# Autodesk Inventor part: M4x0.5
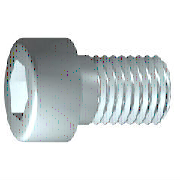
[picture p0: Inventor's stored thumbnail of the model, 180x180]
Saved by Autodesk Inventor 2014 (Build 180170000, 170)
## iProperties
IsCustomPart: 1
Company: 한국ATC센터
Created: 2009-02
Part Number: M4x0.5
Material: 강, 연강
Description: 6각머리 태핑 나사
Document SubType Name: Modeling
Standard: KS B 1003
Designer: KYOUNG IL JANG
Standards Organization: KS
Language: ko-KR
Size Designation: M 4 x 12
Categories: <MemberInstance><Categories><Category DisplayName="조임쇠" InternalName="e4da775c-781d-43d5-af7c-5136215cf5a6" Mnemonic="FSTN"><Category DisplayName="볼트" InternalN
Density: 1 g/cm^3
Appearance: 강철
Author: KYOUNG IL JANG
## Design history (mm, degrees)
sketch "스케치1"
  geometry: L1 (-1, 0)-(12, 0); L2 (12, 0)-(12, 2); L3 (12, 2)-(1.75, 2); L4 (1.75, 2)-(1.32, 2); L5 (1.32, 2)-(0, 2); L6 (0, 2)-(0, 3.5); L7 (0, 3.5)-(-4, 3.5); L8 (-4, 3.5)-(-4, 1.732); L9 (-4, 1.732)-(-2, 1.732); L10 (-2, 1.732)-(-1, 0); L11 (-7.2, 0)-(15.2, 0) reference; L12 (0, -0.7)-(0, 4.2) reference; L13 (1.75, 2)-(0, 2)
  constraints: 22 end point, 6 parallel, 2 collinear, 2 perpendicular, 1 horizontal, 1 point on line
  dimensions: "d1" = 10.25 distance from line of L3.end L2 (= GEL); "d2" = 0.42952 distance of L4.end L3.end (computed from GAL); "d3" = 4 distance between parallel lines of L8 L6 (= KOH); "d4" = 2 distance of L8.end L9.end (= INTI); "d5" = 60 deg angle of L10 L1; "d6" = 4 diameter of L3 L1 (= GD); "d7" = 4 diameter of L5 L1 (= BDM); "d8" = 3.4641 diameter of L9 L1 (= 1.1547 x SW); "d9" = 7 diameter of L7 L1 (= KOD); "d26" = 12 distance between parallel lines of L12 L2 (= NLG)
revolve "본체" sketch "스케치1" stored, may be unused: angle "d10" = 90 deg
sketch "스케치2"
  geometry: L1 (0, -4.9)-(0, 4.9) reference; L2 (-4.9, 0)-(4.9, 0) reference; L3 (1.732, 0)-(0.866, -1.5); L4 (0.866, -1.5)-(-0.866, -1.5); L5 (-0.866, -1.5)-(-1.732, 0); L6 (-1.732, 0)-(-0.866, 1.5); L7 (-0.866, 1.5)-(0.866, 1.5); L8 (0.866, 1.5)-(1.732, 0); 2 further points
  constraints: 12 end point, 1 coincident, 1 horizontal alignment, 1 point on line, 12 other
extrude "슬롯" join sketch "스케치2" stored distance "d11" = 10; taper "d12" = 0 deg
workplane "Work Plane1"
fillet "Fillet2" dims "d30" = 0.1 (= R)
body "Solid1"
fillet "모깎기1" dims "d17" = 0.4 (= RR)
feature "스레드" dims "d13" = 10.25 (= GEL), "d14" = 0
chamfer "모따기1" distance "d15" = 0.42941 (= -0.5 x SPD + 0.5 x GD); stored, may be unused: second distance "d16" = 0.42941 (= GUL), angle "d27" = 45 deg
other parameters: "GD" = 4 (= NND) [user parameter; used in 2 equation terms], "NLG" = 12 [user parameter; used in 1 equation term], "GEL" = 10.25 [user parameter; used in 2 equation terms], "KOD" = 7 [user parameter; used in 1 equation term], "KOH" = 4 [user parameter; used in 1 equation term], "INTI" = 2 [user parameter; used in 1 equation term], "GAL" = 0.42941 (= 0.61345 x PTC) [user parameter; used in 1 equation term], "GUL" = 0.42941 (= 0.61345 x PTC) [user parameter; used in 1 equation term], "BDM" = 4 (= NND) [user parameter; used in 1 equation term], "SW" = 3 [user parameter; used in 2 equation terms], "RR" = 0.4 [user parameter; used in 1 equation term], "SPD" = 3.14117 (= NND - 1.2269 x PTC) [user parameter; used in 1 equation term], "d19" = 0, "d28" = 0, "d29" = 0, "R" = 0.1 [user parameter; used in 1 equation term], "PHH" = 0.2 [user parameter], "GD1" = 3.14117 (= THREADDIA - 1.2269 x PTC) [user parameter], "THREADDIA" = 4 [user parameter; used in 1 equation term], "FAWI" = 45 deg [user parameter], "TPU" = 14.28571 (computed from PTC) [user parameter], "PTC" = 0.7 [user parameter; used in 5 equation terms], "NND" = 4 [user parameter; used in 3 equation terms], "TOA" = 30 deg [user parameter], "E0" = 3.465 (= 1.155 x SW) [user parameter]
